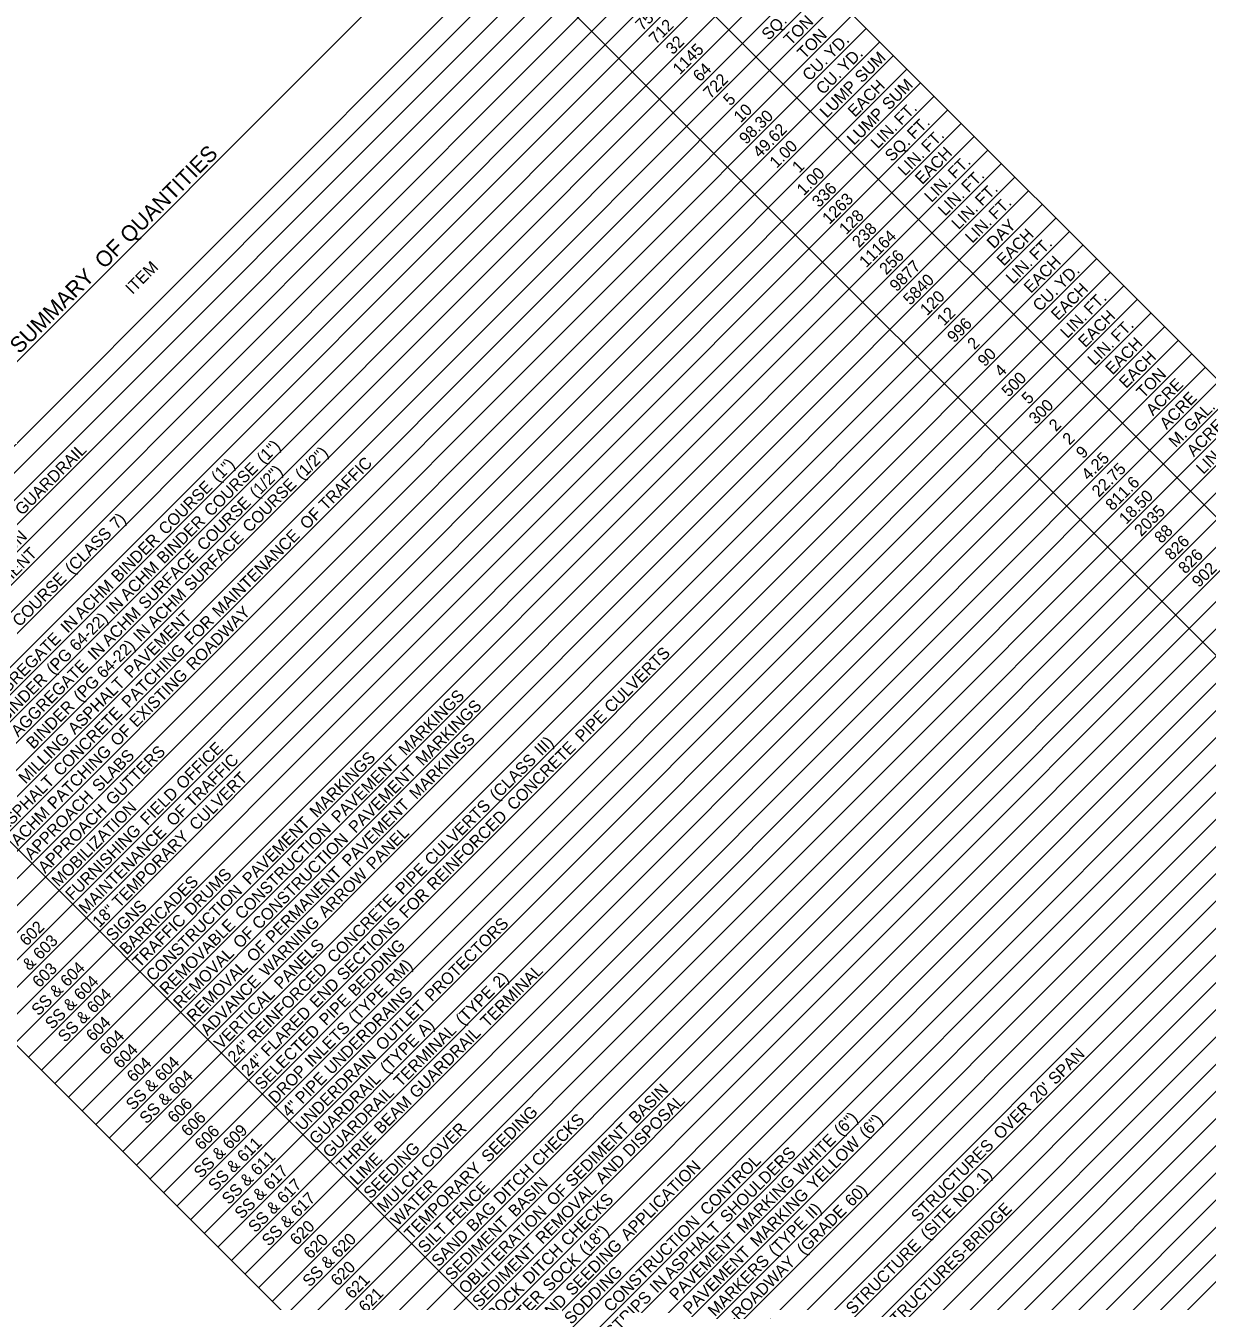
# Model space of a CAD drawing. Extents: x 1675667 to 1681231, y 227227 to 232694.
# Drawn here: x 1679879 to 1680479, y 231542 to 232189 of the extents above; entities that cross this region are included whole.
import ezdxf

# ---------------------------------------------------------------- set-up
doc = ezdxf.new("R2010")
doc.units = 0
doc.layers.add('Default', color=7, linetype='Continuous')

msp = doc.modelspace()

# ---------------------------------------------------------------- linework, layer by layer
at = {"layer": 'Default'}
for p, q in [((1679701.21, 231844.97), (1680174.44, 232318.32)), ((1680739.5, 231753.4), (1680174.44, 232318.32)), ((1679721.89, 231824.29), (1680195.13, 232297.64)), ((1679728.79, 231817.4), (1680202.02, 232290.75)), ((1679735.68, 231810.5), (1680208.92, 232283.85)), ((1680704.34, 231718.24), (1680139.29, 232283.16)), ((1680580.23, 231842.32), (1680139.29, 232283.16)), ((1679742.58, 231803.61), (1680215.81, 232276.96)), ((1679749.47, 231796.72), (1680222.71, 232270.07)), ((1679756.37, 231789.82), (1680229.6, 232263.17)), ((1679763.26, 231782.93), (1680236.5, 232256.28)), ((1679770.16, 231776.04), (1680243.39, 232249.39)), ((1680669.19, 231683.07), (1680104.13, 232247.99)), ((1679777.05, 231769.14), (1680250.29, 232242.49)), ((1679783.95, 231762.25), (1680257.18, 232235.6)), ((1679790.84, 231755.36), (1680264.08, 232228.71)), ((1680545.07, 231807.16), (1680124.81, 232227.31)), ((1679797.74, 231748.46), (1680270.97, 232221.81)), ((1679804.63, 231741.57), (1680277.87, 232214.92)), ((1679811.53, 231734.68), (1680284.76, 232208.03)), ((1679818.42, 231727.78), (1680291.66, 232201.13)), ((1679825.32, 231720.89), (1680298.56, 232194.24)), ((1679832.22, 231714), (1680305.45, 232187.35)), ((1679839.11, 231707.1), (1680312.35, 232180.45)), ((1679846.01, 231700.21), (1680319.24, 232173.56)), ((1679852.9, 231693.32), (1680326.14, 232166.67)), ((1679859.8, 231686.42), (1680333.03, 232159.77)), ((1679866.69, 231679.53), (1680339.93, 232152.88)), ((1679873.59, 231672.63), (1680346.82, 232145.99)), ((1679880.48, 231665.74), (1680353.72, 232139.09)), ((1679887.03, 231659.19), (1680360.27, 232132.54)), ((1679893.93, 231652.3), (1680367.16, 232125.65)), ((1679900.82, 231645.41), (1680374.06, 232118.76)), ((1679907.72, 231638.51), (1680380.95, 232111.86)), ((1679914.61, 231631.62), (1680387.85, 232104.97)), ((1679921.51, 231624.73), (1680394.74, 232098.08)), ((1679928.4, 231617.83), (1680401.64, 232091.18)), ((1679935.3, 231610.94), (1680408.53, 232084.29)), ((1679942.19, 231604.05), (1680415.43, 232077.4)), ((1679949.09, 231597.15), (1680422.32, 232070.5)), ((1679955.98, 231590.26), (1680429.22, 232063.61)), ((1679962.88, 231583.36), (1680436.11, 232056.72)), ((1679969.77, 231576.47), (1680443.01, 232049.82)), ((1679976.67, 231569.58), (1680449.9, 232042.93)), ((1679983.56, 231562.68), (1680456.8, 232036.04)), ((1679990.46, 231555.79), (1680463.69, 232029.14)), ((1679997.35, 231548.9), (1680470.59, 232022.25)), ((1680004.25, 231542), (1680477.48, 232015.36)), ((1680011.14, 231535.11), (1680484.38, 232008.46)), ((1680018.04, 231528.22), (1680491.27, 232001.57)), ((1680024.93, 231521.32), (1680498.17, 231994.67)), ((1680031.83, 231514.43), (1680505.06, 231987.78)), ((1680038.72, 231507.54), (1680511.96, 231980.89)), ((1680045.62, 231500.64), (1680518.85, 231973.99)), ((1680052.51, 231493.75), (1680525.75, 231967.1)), ((1680059.41, 231486.86), (1680532.65, 231960.21)), ((1680066.31, 231479.96), (1680539.54, 231953.31)), ((1680073.2, 231473.07), (1680546.44, 231946.42)), ((1680080.1, 231466.18), (1680553.33, 231939.53)), ((1680086.99, 231459.28), (1680560.23, 231932.63)), ((1680093.89, 231452.39), (1680567.12, 231925.74)), ((1680100.78, 231445.5), (1680574.02, 231918.85)), ((1680107.68, 231438.6), (1680580.91, 231911.95)), ((1680114.57, 231431.71), (1680587.81, 231905.06)), ((1680192.13, 231454.12), (1679751.19, 231894.96)), ((1680121.47, 231424.82), (1680594.7, 231898.17)), ((1680128.36, 231417.92), (1680601.6, 231891.27)), ((1680135.26, 231411.03), (1680608.49, 231884.38)), ((1680142.15, 231404.14), (1680615.39, 231877.49)), ((1680192.13, 231454.12), (1679771.87, 231874.28)), ((1680149.05, 231397.24), (1680622.28, 231870.59)), ((1680155.94, 231390.35), (1680629.18, 231863.7)), ((1680162.84, 231383.45), (1680636.07, 231856.81)), ((1680169.73, 231376.56), (1680642.97, 231849.91)), ((1680266.26, 231280.05), (1679701.21, 231844.97)), ((1680266.26, 231280.05), (1679701.21, 231844.97)), ((1680176.63, 231369.67), (1680649.86, 231843.02)), ((1680183.52, 231362.77), (1680656.76, 231836.13)), ((1680190.42, 231355.88), (1680663.65, 231829.23)), ((1680197.31, 231348.99), (1680670.55, 231822.34)), ((1680204.21, 231342.09), (1680677.44, 231815.45)), ((1680211.1, 231335.2), (1680684.34, 231808.55)), ((1680218, 231328.31), (1680691.23, 231801.66)), ((1680224.89, 231321.41), (1680698.13, 231794.77)), ((1680231.79, 231314.52), (1680705.02, 231787.87)), ((1680238.68, 231307.63), (1680711.92, 231780.98))]:
    msp.add_line(p, q, dxfattribs=at)

# ---------------------------------------------------------------- texts
for s, height, p in [('750', 6, (1680191.91, 232185.79)), ('SQ.', 6, (1680255.99, 232180.94)), ('TON', 6, (1680267.22, 232178.38)), ('712', 6, (1680198.82, 232178.91)), ('TON', 6, (1680274.11, 232171.49)), ('32', 6, (1680207.36, 232173.67)), ('1145', 6, (1680210.92, 232163.44)), (' YD.', 6, (1680286.36, 232169.95)), (' YD.', 6, (1680293.26, 232163.06)), (' SUM', 6, (1680301.73, 232157.74)), ('64', 6, (1680221.14, 232159.87)), ('CU.', 6, (1680276.67, 232160.26)), ('722', 6, (1680226.4, 232151.34)), ('CU.', 6, (1680283.57, 232153.37)), ('LUMP', 6, (1680285.52, 232141.53)), ('EACH', 6, (1680299.71, 232141.93)), (' SUM', 6, (1680315.52, 232143.96)), ('5', 6, (1680236.55, 232147.7)), ('10', 6, (1680241.82, 232139.19)), ('LUMP', 6, (1680299.31, 232127.74)), (' FT.', 6, (1680321.67, 232136.31)), ('98.30', 6, (1680244.6, 232128.18)), (' FT.', 6, (1680328.23, 232129.09)), ('49.62', 6, (1680251.51, 232121.3)), ('LIN.', 6, (1680311.32, 232125.96)), (' FT.', 6, (1680335.46, 232122.53)), (' QUANTITIES', 8, (1679929.61, 232075.7)), ('1.00', 6, (1680260.03, 232116.04)), ('SQ.', 6, (1680318.54, 232119.39)), ('EACH', 6, (1680333.84, 232107.81)), ('LIN.', 6, (1680325.11, 232112.17)), (' FT.', 6, (1680348.9, 232109.08)), ('1', 6, (1680271.45, 232113.66)), ('1.00', 6, (1680273.82, 232102.25)), (' FT.', 6, (1680355.8, 232102.19)), ('336', 6, (1680281.53, 232096.17)), ('LIN.', 6, (1680338.55, 232098.73)), (' FT.', 6, (1680362.69, 232095.3)), ('1263', 6, (1680286.78, 232087.63)), ('LIN.', 6, (1680345.45, 232091.84)), ('128', 6, (1680295.32, 232082.38)), ('LIN.', 6, (1680352.34, 232084.94)), (' FT.', 6, (1680369.59, 232088.4)), ('238', 6, (1680301.87, 232075.83)), ('LIN.', 6, (1680359.24, 232078.05)), ('DAY', 6, (1680370.24, 232075.27)), ('11164', 6, (1680305.49, 232065.66)), ('EACH', 6, (1680375.21, 232066.45)), (' OF', 8, (1679916.81, 232062.89)), (' FT.', 6, (1680390.27, 232067.72)), ('ITEM', 6, (1679933.25, 232052.15)), ('256', 6, (1680315.67, 232062.05)), ('9877', 6, (1680320.91, 232053.51)), ('LIN.', 6, (1680379.92, 232057.37)), ('EACH', 6, (1680389, 232052.66)), (' SUMMARY', 8, (1679873.77, 232019.84)), ('5840', 6, (1680327.82, 232046.62)), (' YD.', 6, (1680403.24, 232053.11)), ('EACH', 6, (1680402.8, 232038.88)), ('120', 6, (1680336.36, 232041.38)), ('CU.', 6, (1680393.55, 232043.42)), (' FT.', 6, (1680417.85, 232040.15)), ('12', 6, (1680344.92, 232036.15)), ('EACH', 6, (1680416.59, 232025.09)), ('996', 6, (1680350.14, 232027.58)), ('LIN.', 6, (1680407.5, 232029.8)), (' FT.', 6, (1680431.64, 232026.36)), ('2', 6, (1680360.35, 232024.01)), ('EACH', 6, (1680430.38, 232011.3)), ('90', 6, (1680365.59, 232015.45)), ('LIN.', 6, (1680421.29, 232016.01)), ('EACH', 6, (1680437.27, 232004.41)), ('4', 6, (1680374.13, 232010.21)), ('500', 6, (1680377.73, 232000.02)), ('TON', 6, (1680446.15, 231999.5)), ('ACRE', 6, (1680450.98, 231990.54)), ('5', 6, (1680387.9, 231996.39)), ('300', 6, (1680391.52, 231986.23)), ('ACRE', 6, (1680457.88, 231983.65)), (' GAL.', 6, (1680468.56, 231980.55)), ('2', 6, (1680401.72, 231982.65)), ('ACRE', 6, (1680471.67, 231969.86)), ('2', 6, (1680408.62, 231975.75)), ('M.', 6, (1680462.5, 231974.48)), (' GUARDRAIL', 6, (1679875.71, 231938.47)), (' (1")', 6, (1679998.28, 231964.54)), (' (1/2")', 6, (1680017.76, 231956.45)), ('9', 6, (1680415.49, 231968.83)), ('4.25', 6, (1680418.25, 231957.81)), ('LIN.', 6, (1680476.45, 231960.86)), (' COURSE', 6, (1679971.59, 231937.84)), (' (1")', 6, (1679975.18, 231955.22)), (' (1/2")', 6, (1679994.66, 231947.13)), (' TRAFFIC', 6, (1680029.79, 231940.9)), ('22.75', 6, (1680423.5, 231949.27)), (' COURSE', 6, (1679991.07, 231929.75)), ('811.6', 6, (1680430.41, 231942.39)), (' COURSE', 6, (1679948.49, 231928.53)), ('18.50', 6, (1680437.32, 231935.5)), (' COURSE', 6, (1679967.97, 231920.44)), (' 7)', 6, (1679923.8, 231931.41)), (' BINDER', 6, (1679947.63, 231913.87)), (' OF', 6, (1680020.19, 231931.29)), ('2035', 6, (1680445.01, 231929.41)), (' EXCAVATION', 6, (1679842.12, 231891.09)), (' (CLASS', 6, (1679901.05, 231908.66)), (' MAINTENANCE', 6, (1679975.71, 231886.81)), ('88', 6, (1680455.21, 231925.82)), (' BINDER', 6, (1679924.53, 231904.56)), (' SURFACE', 6, (1679961.42, 231900.09)), ('826', 6, (1680460.46, 231917.29)), (' EMBANKMENT', 6, (1679843.75, 231878.92)), (' SURFACE', 6, (1679938.32, 231890.77)), ('826', 6, (1680467.36, 231910.39)), (' ACHM', 6, (1679928.97, 231895.22)), ('902', 6, (1680474.28, 231903.52)), (' COURSE', 6, (1679874.36, 231881.96)), (' ACHM', 6, (1679905.87, 231885.9)), (' ACHM', 6, (1679942.76, 231881.43)), (' ACHM', 6, (1679919.66, 231872.11)), (' IN', 6, (1679921.89, 231888.13)), (' ROADWAY', 6, (1679962.6, 231859.9)), (' IN', 6, (1679898.79, 231878.81)), (' 64-22)', 6, (1679903.33, 231869.57)), (' PAVEMENT', 6, (1679931.02, 231855.9)), (' FOR', 6, (1679961.63, 231872.72)), (' AGGREGATE', 6, (1679859.91, 231839.92)), (' IN', 6, (1679935.68, 231874.34)), (' IN', 6, (1679912.58, 231865.03)), (' 64-22)', 6, (1679917.12, 231855.78)), (' PATCHING', 6, (1679929.73, 231840.81)), (' (PG', 6, (1679891.52, 231857.75)), (' CULVERTS', 6, (1680174.65, 231838.26)), (' AGGREGATE', 6, (1679873.7, 231826.14)), (' EXISTING', 6, (1679933.65, 231830.95)), (' BINDER', 6, (1679867.56, 231833.79)), (' ASPHALT', 6, (1679902.48, 231827.35)), (' (PG', 6, (1679905.31, 231843.97)), (' MARKINGS', 6, (1680070.27, 231816.59)), (' BINDER', 6, (1679881.35, 231820)), (' CONCRETE', 6, (1679895.14, 231806.21)), (' MARKINGS', 6, (1680078.97, 231811.5)), (' PIPE', 6, (1680159.82, 231823.42)), (' MILLING', 6, (1679877.5, 231802.36)), (' OF', 6, (1679924.05, 231821.34)), (' MARKINGS', 6, (1680075.7, 231794.44)), (' PATCHING', 6, (1679892.15, 231789.43)), (' GUTTERS', 6, (1679921.72, 231791.43)), (' OFFICE', 6, (1679957.36, 231799.49)), (' CONCRETE', 6, (1680125.22, 231788.82)), (' III)', 6, (1680139.19, 231816.58)), (' SLABS', 6, (1679914.83, 231798.32)), (' TRAFFIC', 6, (1679962.05, 231790.4)), (' MARKINGS', 6, (1680025.15, 231785.25)), (' PAVEMENT', 6, (1680036.13, 231782.44)), (' (CLASS', 6, (1680116.44, 231793.82)), (' CULVERT', 6, (1679964.07, 231778.63)), (' PAVEMENT', 6, (1680044.83, 231777.35)), ('ASPHALT', 6, (1679868.24, 231779.31)), ('APPROACH', 6, (1679882.03, 231765.52)), (' FIELD', 6, (1679939.23, 231781.36)), (' PAVEMENT', 6, (1680041.56, 231760.29)), ('ACHM', 6, (1679875.14, 231772.42)), ('APPROACH', 6, (1679888.93, 231758.63)), ('MOBILIZATION', 6, (1679895.82, 231751.74)), (' OF', 6, (1679952.44, 231780.79)), (' CULVERTS', 6, (1680083.48, 231760.86)), (' CONSTRUCTION', 6, (1679987.22, 231733.52)), (' PAVEMENT', 6, (1679991.01, 231751.1)), (' REINFORCED', 6, (1680084.7, 231748.29)), ('FURNISHING', 6, (1679902.72, 231744.84)), ('MAINTENANCE', 6, (1679909.61, 231737.95)), (' TEMPORARY', 6, (1679924.93, 231739.47)), (' CONSTRUCTION', 6, (1679995.92, 231728.43)), (' PANEL', 6, (1680053.89, 231758.84)), (' DRUMS', 6, (1679961.64, 231735.52)), (' PERMANENT', 6, (1680002.81, 231721.54)), (' ARROW', 6, (1680029.59, 231734.53)), (' PIPE', 6, (1680068.65, 231746.02)), ('BARRICADES', 6, (1679930.3, 231717.27)), ('CONSTRUCTION', 6, (1679943.74, 231703.83)), (' CONCRETE', 6, (1680034.05, 231711.41)), (' FOR', 6, (1680070.63, 231734.21)), ('18"', 6, (1679916.51, 231731.06)), ('SIGNS', 6, (1679923.4, 231724.16)), (' 602', 6, (1679877.99, 231720.11)), ('TRAFFIC', 6, (1679936.85, 231710.72)), ('REMOVABLE', 6, (1679950.64, 231696.93)), (' WARNING', 6, (1679999.67, 231704.6)), (' SECTIONS', 6, (1680038.99, 231702.56)), (' PROTECTORS', 6, (1680083.54, 231691.96)), (' 603', 6, (1679884.84, 231713.17)), (' OF', 6, (1679986.31, 231718.82)), ('REMOVAL', 6, (1679957.54, 231690.04)), (' OF', 6, (1679993.21, 231711.93)), (' PANELS', 6, (1680007, 231698.14)), (' BEDDING', 6, (1680044.72, 231694.51)), (' &', 6, (1679879.37, 231707.7)), ('603', 6, (1679886.02, 231700.56)), (' 604', 6, (1679898.64, 231699.39)), (' RM)', 6, (1680063.54, 231699.54)), (' 604', 6, (1679905.53, 231692.5)), ('REMOVAL', 6, (1679964.43, 231683.15)), ('ADVANCE', 6, (1679971.33, 231676.25)), (' REINFORCED', 6, (1679993.53, 231670.88)), (' TERMINAL', 6, (1680111.76, 231678.82)), (' 2)', 6, (1680117.95, 231698.8)), (' &', 6, (1679893.17, 231693.92)), (' 604', 6, (1679912.08, 231685.95)), (' END', 6, (1680025.14, 231688.71)), (' UNDERDRAINS', 6, (1680032.66, 231654.86)), (' (TYPE', 6, (1680044.76, 231680.75)), (' (TYPE', 6, (1680099.16, 231680.01)), ('SS', 6, (1679885.57, 231686.32)), (' &', 6, (1679900.07, 231687.03)), ('VERTICAL', 6, (1679978.22, 231669.36)), (' PIPE', 6, (1680029.88, 231679.67)), (' OUTLET', 6, (1680058.63, 231667.04)), ('SS', 6, (1679892.47, 231679.43)), (' &', 6, (1679906.62, 231680.48)), (' FLARED', 6, (1680000.43, 231663.99)), ('SS', 6, (1679899.02, 231672.88)), ('604', 6, (1679913.27, 231673.34)), ('SELECTED', 6, (1679998.91, 231648.68)), (' INLETS', 6, (1680022.67, 231658.66)), (' TERMINAL', 6, (1680067.76, 231648.59)), (' A)', 6, (1680079.65, 231674.28)), ('604', 6, (1679920.16, 231666.45)), ('24"', 6, (1679985.12, 231662.47)), (' (TYPE', 6, (1680060.86, 231655.49)), (' GUARDRAIL', 6, (1680075.74, 231642.79)), ('604', 6, (1679927.06, 231659.56)), ('24"', 6, (1679992.01, 231655.57)), ('UNDERDRAIN', 6, (1680019.59, 231628)), (' SPAN', 6, (1680399.84, 231649.79)), ('604', 6, (1679933.95, 231652.66)), (' 604', 6, (1679946.56, 231651.48)), ('DROP', 6, (1680005.8, 231641.79)), (' 604', 6, (1679953.45, 231644.59)), (' PIPE', 6, (1680017.82, 231640.02)), ('GUARDRAIL', 6, (1680026.49, 231621.11)), ('SS', 6, (1679933.49, 231638.41)), (' &', 6, (1679941.09, 231646.01)), ('GUARDRAIL', 6, (1680033.38, 231614.21)), (' BASIN', 6, (1680187.08, 231630.05)), (" 20'", 6, (1680390.45, 231640.4)), ('SS', 6, (1679940.39, 231631.52)), (' &', 6, (1679947.99, 231639.12)), ('606', 6, (1679954.63, 231631.97)), ('4"', 6, (1680012.7, 231634.89)), (' BEAM', 6, (1680057.74, 231624.79)), (' DISPOSAL', 6, (1680184.01, 231613.18)), (' OVER', 6, (1680372.04, 231621.98)), ('606', 6, (1679961.52, 231625.08)), (' SEEDING', 6, (1680112.26, 231610.36)), (' CHECKS', 6, (1680137.77, 231608.3)), (' (6")', 6, (1680291.15, 231623.82)), (' (6")', 6, (1680303.9, 231622.78)), ('606', 6, (1679968.42, 231618.19)), (' 609', 6, (1679981.02, 231617)), (' COVER', 6, (1680081.56, 231607.24)), (' SEDIMENT', 6, (1680154.93, 231597.89)), (' 611', 6, (1679988.33, 231610.52)), ('THRIE', 6, (1680040.28, 231607.32)), (' WHITE', 6, (1680270.73, 231603.39)), (' YELLOW', 6, (1680277.62, 231596.5)), ('STRUCTURES', 6, (1680331.82, 231581.75)), (' &', 6, (1679975.56, 231611.53)), (' 611', 6, (1679995.22, 231603.63)), ('LIME', 6, (1680047.17, 231600.43)), ('SEEDING', 6, (1680054.07, 231593.53)), (' SHOULDERS', 6, (1680233.36, 231579.8)), ('SS', 6, (1679967.96, 231603.93)), (' &', 6, (1679982.87, 231605.05)), (' 617', 6, (1680001.71, 231596.32)), ('MULCH', 6, (1680060.96, 231586.64)), ('TEMPORARY', 6, (1680074.75, 231572.85)), (' DITCH', 6, (1680118.49, 231589.02)), (' AND', 6, (1680170.16, 231599.33)), (' APPLICATION', 6, (1680182.91, 231570.72)), (' CONTROL', 6, (1680223.2, 231583.43)), ('SS', 6, (1679975.27, 231597.45)), (' &', 6, (1679989.76, 231598.16)), (' 617', 6, (1680008.6, 231589.43)), ('WATER', 6, (1680067.86, 231579.74)), (' FENCE', 6, (1680094.04, 231578.36)), (' BASIN', 6, (1680125.95, 231582.69)), (' MARKING', 6, (1680241.79, 231574.44)), (' 1)', 6, (1680363.17, 231599.32)), ('SS', 6, (1679982.16, 231590.56)), (' &', 6, (1679996.24, 231590.86)), (' 617', 6, (1680015.5, 231582.53)), (' REMOVAL', 6, (1680139.74, 231568.9)), (' OF', 6, (1680145.32, 231588.28)), (' MARKING', 6, (1680248.68, 231567.55)), (' 60)', 6, (1680296.66, 231587.96)), (' NO.', 6, (1680351.5, 231587.65)), ('SS', 6, (1679988.65, 231583.26)), (' &', 6, (1680003.14, 231583.96)), ('OBLITERATION', 6, (1680102.33, 231545.28)), (' BAG', 6, (1680104.7, 231575.22)), (' CHECKS', 6, (1680152.51, 231567.89)), (' (GRADE', 6, (1680272.28, 231563.58)), (' II)', 6, (1680276.61, 231581.7)), (' STRUCTURES-BRIDGE', 6, (1680315.83, 231524.39)), (' (SITE', 6, (1680335.03, 231571.17)), ('SS', 6, (1679995.54, 231576.36)), (' &', 6, (1680010.03, 231577.07)), ('SEDIMENT', 6, (1680095.44, 231552.17)), (' CONSTRUCTION', 6, (1680174.29, 231534.51)), (' (TYPE', 6, (1680257.83, 231562.91)), ('SS', 6, (1680002.44, 231569.47)), ('620', 6, (1680016.69, 231569.94)), ('SILT', 6, (1680081.65, 231565.96)), ('SAND', 6, (1680088.54, 231559.06)), (' (18")', 6, (1680161.79, 231563.38)), (' ASPHALT', 6, (1680204.82, 231551.26)), (' PAVEMENT', 6, (1680207.65, 231540.3)), ('620', 6, (1680023.59, 231563.05)), (' 620', 6, (1680036.19, 231561.86)), ('SEDIMENT', 6, (1680109.23, 231538.38)), (' DITCH', 6, (1680133.24, 231548.61)), (' SEEDING', 6, (1680154.96, 231542.76)), (' STRUCTURE', 6, (1680297.14, 231533.28)), (' &', 6, (1680030.73, 231556.4)), (' SOCK', 6, (1680143.36, 231544.94)), (' PAVEMENT', 6, (1680214.54, 231533.4)), (' STEEL-ROADWAY', 6, (1680219.3, 231510.58)), (' MARKERS', 6, (1680227.18, 231532.25)), ('SS', 6, (1680023.13, 231548.8)), ('620', 6, (1680037.38, 231549.26)), (' SODDING', 6, (1680154.28, 231528.28)), ('621', 6, (1680044.68, 231542.77)), ('ROCK', 6, (1680116.12, 231531.49)), (' IN', 6, (1680197.73, 231544.17)), ('621', 6, (1680051.57, 231535.88)), ('FILTER', 6, (1680123.02, 231524.6)), ('SECOND', 6, (1680129.91, 231517.7)), (' STRIPS', 6, (1680174.98, 231521.42))]:
    msp.add_text(s, height=height, rotation=45.00703, dxfattribs=at).set_placement(p)

doc.saveas('drawing.dxf')
